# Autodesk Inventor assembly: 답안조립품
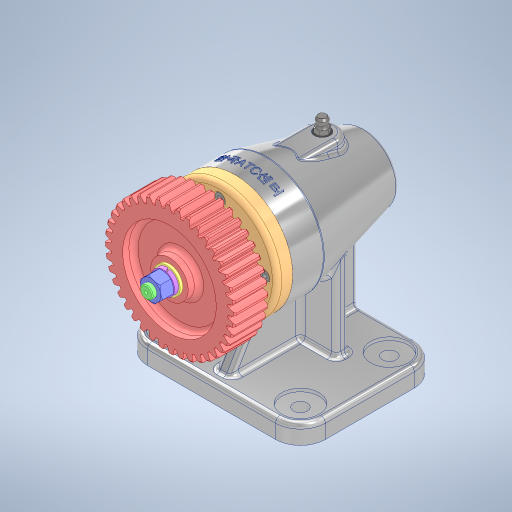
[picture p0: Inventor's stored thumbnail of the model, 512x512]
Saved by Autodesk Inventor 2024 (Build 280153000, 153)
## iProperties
Created: 2024-12
Part Number: 답안조립품
Document SubType Name: Assembly
Designer: user
Author: user
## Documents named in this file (15)
- C:\Users\user\Desktop\741204V1018\답안조립품.iam
- C:\Users\user\Desktop\741204V1018\01본체.ipt
- C:\Users\user\Desktop\741204V1018\그리스 니플 M6x0.75\그리스 니플 M6x0.75.ipt
- C:\Users\user\Desktop\741204V1018\스퍼기어\스퍼기어.ipt
- C:\Users\user\Desktop\741204V1018\스프링 와셔 M8\스프링 와셔 M8.ipt
- C:\Users\user\Desktop\741204V1018\실링\실링.ipt
- C:\Users\user\Desktop\741204V1018\앵귤러 볼 베어링 7003A\앵귤러 볼 베어링 7003A.ipt
- C:\Users\user\Desktop\741204V1018\앵귤러 볼 제어링 7204A\앵귤러 볼 제어링 7204A.ipt
- C:\Users\user\Desktop\741204V1018\오일 실 20 32 8\오일 실 20 32 8.ipt
- C:\Users\user\Desktop\741204V1018\육각 너트 M8\육각 너트 M8.ipt
- C:\Users\user\Desktop\741204V1018\육각 소켓 머리 볼트 M4x10\육각 소켓 머리 볼트 M4x10.ipt
- C:\Users\user\Desktop\741204V1018\축\축.ipt
- C:\Users\user\Desktop\741204V1018\커버\커버.ipt
- C:\Users\user\Desktop\741204V1018\평와셔 M8\평와셔 M8.ipt
- C:\Users\user\Desktop\741204V1018\평행 키 4x4x14\평행 키 4x4x14.ipt
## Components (2 placed, 2 different names)
1. 01본체:1
2. 그리스 니플 M6x0.75:1 — 각도:1
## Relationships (1: Angle 1)
- 각도:1 [Angle]: 그리스 니플 M6x0.75:1
